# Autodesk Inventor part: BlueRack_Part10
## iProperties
Shininess: 64.0
Length Units: 11272
Angle Units: 11279
Time Units: 11290
Mass Units: 11286
Length Display Precision: 3
Angle Display Precision: 2
Compacted: True
Part Number: BlueRack_Part10
Document SubType Name: Modeling
Created: 2004-12
Designer: John Blackburn
Material: Steel, Mild
Manufacturer: Standard
Standards Organization: Custom
Density: 0.0
Volumn: 0.0
Area: 0.0
PropertySet Name: Model Information
Control State: 0
Master: False
Checked Out: False
Author: John Blackburn
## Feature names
1. Extrusion1
